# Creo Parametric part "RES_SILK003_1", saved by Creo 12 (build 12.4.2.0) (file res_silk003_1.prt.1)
Units: Custom; MM, KILOGRAM, SECS

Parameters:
  PTC_WM_ITERATION = "0"
  PTC_WM_VERSION = "-.0"
  PTC_WM_LIFECYCLE_STATE = "In Work"
  PTC_WM_LIFECYCLE = "MO_CADDocument"
  PTC_WM_CREATED_BY = "Maximilian Roepper (Z0017RMS: MO)"
  PTC_WM_CREATED_ON = "18-Sep-26 11:36:42 AM"
  PTC_WM_MODIFIED_BY = "Maximilian Roepper (Z0017RMS: MO)"
  PTC_WM_MODIFIED_ON = "18-Sep-26 11:36:46 AM"
  PDMLINKNUMBER = "PDM000071455292"
  PTC_WM_NAME = "res_silk003_1.prt"
  PTC_WM_NUMBER = "PDM000071455292"

Other parameters: WEIGHT, WEIGHT_FACTOR, WEIGHT_ADD, _MASS_TEMP, _DIFF_TEMP, MC_ERRORS, SUPPLIER

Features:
  1. coordinate system
  2. datum plane "PRT_YZ"
  3. datum plane "PRT_XY"
  4. datum plane "PRT_XZ"
  5. coordinate system
  6. datum axis
  7. datum axis
  8. datum axis
  9. coordinate system
  10. imported feature

Other named items: PRT, SIEMENS_MO, DRW_VIEW_ORG, PRT_X, PRT_Y, PRT_Z, CS0, ROUGH_GROB

Layers: 00_STD_CSYS-KSYS, 01_STD_PLANES-EBENEN, 02_STD_AXES-ACHSEN, 03_STD_CSYS-KSYS, 24_IMPORT_FEAT-IMPORT_KE

Surfaces: 10 plane, 8 cylinder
